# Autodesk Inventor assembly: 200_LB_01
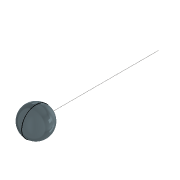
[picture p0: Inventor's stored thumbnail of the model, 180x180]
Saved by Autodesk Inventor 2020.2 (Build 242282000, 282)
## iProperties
Manager: www.cadconsulting.pl
Company: Fabian Stasiak CAD Consulting
Created: 2020-03
Part Number: 200_LB_01
Document SubType Name: Konstrukcja spawana
Designer: F.Stasiak
Weld Material: Aluminium 6061, spawane
Mass: 380.238 g
Surface Area: 52.6256 cm^2
Volume: 33.5398 cm^3
Density: 11.3369 g/cm^3
Catalog Web Link: www.expertbooks.pl
Author: F.Stasiak
Subject: Zbiór ćwiczeń. Autodesk Inventor 2020. Kurs Professional
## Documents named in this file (3)
- C:\2020_Kurs_Professional\R3 Dynamika\Komponenty_dyn\200_LB_01.iam
- C:\2020_Kurs_Professional\R3 Dynamika\Komponenty_dyn\200_01_Kulka.ipt
- C:\2020_Kurs_Professional\R3 Dynamika\Komponenty_dyn\200_01_Link.ipt
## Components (2 placed, 2 different names)
1. 200_01_Kulka:1
2. 200_01_Link:1 — Zestawiające:3, Równoległe:2, Równoległe:3
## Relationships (3: Flush 2, Mate 1)
- Zestawiające:3 [Mate]: 200_01_Link:1
- Równoległe:2 [Flush]: 200_01_Link:1
- Równoległe:3 [Flush]: 200_01_Link:1
